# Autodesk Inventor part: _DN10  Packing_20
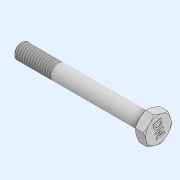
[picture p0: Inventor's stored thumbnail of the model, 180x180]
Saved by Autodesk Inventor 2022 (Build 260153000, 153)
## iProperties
Created: 2021-12
Part Number: _DN10  Packing_20
Material: Generico
Document SubType Name: Modeling
Designer: admin
Density: 1 g/cm^3
Appearance: Default
Author: admin
Revision Number: NONE
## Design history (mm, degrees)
node "_DN10  Packing"
sketch "Schizzo1"
  geometry: C1 r 3 at (0, 0) reference; 2 further points
extrude "Estrusione1" join sketch "Schizzo1" distance "d2" = 6; taper "d3" = 0 deg
feature "Filettatura2" dims "d4" = 15, "d5" = 0
chamfer "Smusso1" distance "d6" = 0.4; stored, may be unused: second distance "d7" = 2, angle "d8" = 45 deg
node "Solido1"
node "Linea chiusa proiettata1"
